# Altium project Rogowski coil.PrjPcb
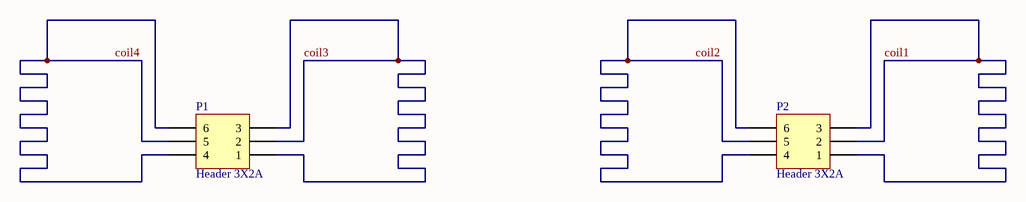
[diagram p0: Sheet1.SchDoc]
1 sheet, 2 parts. Net scope: global (net labels, ports and power ports of the same name join across sheets).
Board file: PCB1.PcbDoc

## Sheet Sheet1.SchDoc
size A4; SheetNumber: 1; SheetTotal: 1

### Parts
P1  Header 3X2A  [HDR2X3_CEN]
P2  Header 3X2A  [HDR2X3_CEN]

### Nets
coil1: P2.1 P2.2 P2.3
coil2: P2.4 P2.5 P2.6
coil3: P1.1 P1.2 P1.3
coil4: P1.4 P1.5 P1.6

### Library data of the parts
P1 P2 = Header 3X2A: Header, 3-Pin, Dual row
